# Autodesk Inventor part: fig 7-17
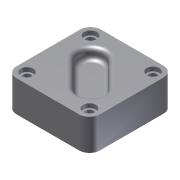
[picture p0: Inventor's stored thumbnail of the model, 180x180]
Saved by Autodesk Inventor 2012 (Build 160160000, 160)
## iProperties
Shininess: 77.0
Angle Display Precision: 2
Document Length Units: 11269
Document Angle Units: 11279
Document Time Units: 11290
Document Mass Units: 11283
Document Length Units Precision: 3
Document Angle Units Precision: 2
Created: 2001-12
Part Number: fig 7-17
Document SubType Name: Modeling
Designer: Renu Muthoo
Density: 1 g/cm^3
Material: Default
Density: 0.0
Volumn: 0.0
Area: 0.0
PropertySet Name: Model Information
Control State: 0
Master: False
Checked Out: False
Author: Renu Muthoo
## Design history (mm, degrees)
sketch "Sketch1"
  geometry: L1 (-20, 20)-(20, 20); L2 (20, 20)-(20, -20.5); L3 (20, -20.5)-(-20, -20.5); L4 (-20, -20.5)-(-20, 20); 1 further point
  constraints: 8 end point, 2 parallel, 1 horizontal, 1 perpendicular, 1 other
  dimensions: "d0" = 40 distance of L1.start L1.end; "d1" = 40.5 distance of L3.end L1.start; "d100" = 20 distance from line of L4 point (0, 0); "d101" = 20 distance from line of L1 point (0, 0)
extrude "Extrusion1" new body sketch "Sketch1" distance "d2" = 15; taper "d3" = 0 deg
workplane "Work Plane1"
workplane "Work Plane2"
workplane "Work Plane3"
fillet "Fillet1" dims "d32" = 5
hole "Hole3" diameter "d66" = 4; stored, may be unused: countersink angle "d70" = 90 deg, drill point angle "d72" = 118 deg; dims "d64" = 10, "d65" = 10, "d67" = 6, "d68" = 6, "d69" = 2, "d71" = 8
hole "Hole4" diameter "d75" = 4; stored, may be unused: countersink angle "d79" = 90 deg, drill point angle "d81" = 118 deg; dims "d73" = 10, "d74" = 10, "d76" = 6, "d77" = 6, "d78" = 2, "d80" = 8
hole "Hole5" diameter "d84" = 4; stored, may be unused: countersink angle "d88" = 90 deg, drill point angle "d90" = 118 deg; dims "d82" = 10, "d83" = 10, "d85" = 6, "d86" = 6, "d87" = 2, "d89" = 8
hole "Hole6" diameter "d93" = 4; stored, may be unused: countersink angle "d97" = 90 deg, drill point angle "d99" = 118 deg; dims "d91" = 10, "d92" = 10, "d94" = 6, "d95" = 6, "d96" = 2, "d98" = 8
fillet "Fillet2" dims "d61" = 2
body "Solid1"
sketch "Sketch8"
  geometry: L1 (-9.844, 1.64)-(1.983, -10.187); L2 (10.469, -1.701)-(-1.358, 10.126); A1 r 6 centre (-5.601, 5.883) between (-1.358, 10.126) and (-9.844, 1.64); A2 r 6 centre (6.226, -5.944) between (1.983, -10.187) and (10.469, -1.701)
  constraints: 4 end point, 4 point on circle, 4 tangent, 2 centre point, 1 parallel
  dimensions: "d29" = 6 radius of A2
extrude "Extrusion2" cut sketch "Sketch8" distance "d30" = 5; taper "d31" = 0 deg
